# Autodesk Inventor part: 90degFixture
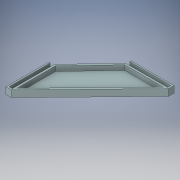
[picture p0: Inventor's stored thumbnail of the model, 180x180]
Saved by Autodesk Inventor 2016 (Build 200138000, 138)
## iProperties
Created: 2015-11
Part Number: 90degFixture
Material: Generic
Document SubType Name: Modeling
Designer: John
Density: 1 g/cm^3
Appearance: Default
Author: John
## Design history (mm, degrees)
feature "Base1"
sketch "Sketch1"
  geometry: L1 (-1.557, -10.1)-(85.8, -10.1) reference; L2 (-73.95, -86.546)-(-1.557, -10.1) reference; L3 (-73.95, -174.2)-(-73.95, -86.546) reference; L4 (-80.8, -174.2)-(-73.95, -174.2) reference; L5 (-80.8, -88.4)-(-80.8, -174.2) reference; L6 (-84.05, -88.4)-(-80.8, -88.4) reference; L7 (-84.05, -177.45)-(-84.05, -88.4) reference; L8 (-72.723, -177.45)-(-84.05, -177.45) reference; L9 (89.05, -11.272)-(-72.723, -177.45) reference; L10 (89.05, 0)-(89.05, -11.272) reference; L11 (0, 0)-(89.05, 0) reference; L12 (0, -3.25)-(0, 0) reference; L13 (85.8, -3.25)-(0, -3.25) reference; L14 (85.8, -10.1)-(85.8, -3.25) reference; L15 (0.164, -14.1)-(80.715, -14.1); L16 (80.715, -14.1)-(-69.95, -168.867); L17 (-69.95, -168.867)-(-69.95, -88.139); L18 (-69.95, -88.139)-(0.164, -14.1); 1 further point
  constraints: 8 end point, 3 other
  dimensions: "d0" = 4 distance between parallel lines of L2 L18
extrude "Extrusion1" cut sketch "Sketch1" distance "d1" = 10; taper "d2" = 0 deg
body "Solid1"
node "Projected Loop1"
